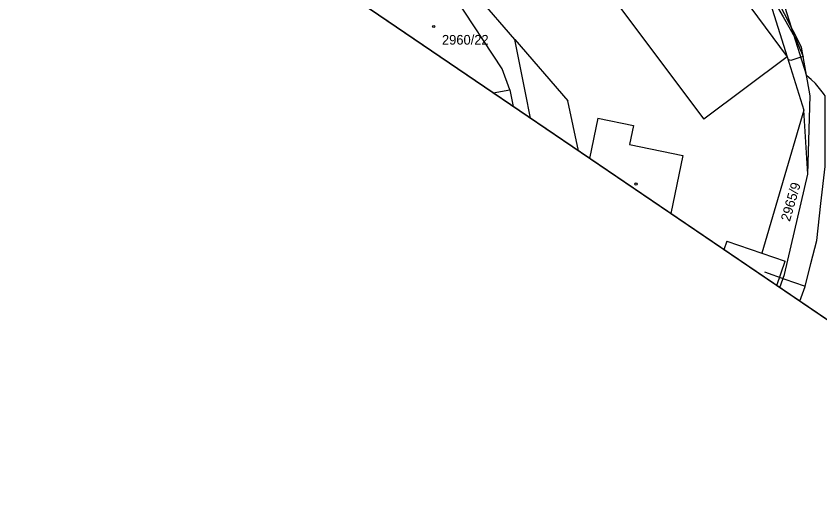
# Model space of a CAD drawing. Extents: x -620624 to -619936, y -1122925 to -1122325.
# Drawn here: x -620469.2 to -620344.4, y -1122791.5 to -1122714.1 of the extents above; entities that cross this region are included whole.
import ezdxf

# ---------------------------------------------------------------- set-up
doc = ezdxf.new("R2010")
doc.units = 0
for name, color, linetype in [('GasNet', 7, 'Continuous'), ('RÁMY', 7, 'Continuous'), ('VAS vodovod', 7, 'Continuous'), ('Vrstva 55', 7, 'Continuous'), ('Vrstva 57', 7, 'Continuous')]:
    doc.layers.add(name, color=color, linetype=linetype)

msp = doc.modelspace()

# ---------------------------------------------------------------- linework, layer by layer
at = {"layer": 'GasNet'}
msp.add_lwpolyline([(-620351, -1122709.02), (-620351.62, -1122709.36), (-620351.95, -1122709.89), (-620351.89, -1122710.61), (-620351.38, -1122712.06), (-620350.09, -1122714.22), (-620348.14, -1122717.64), (-620346.99, -1122720.36), (-620347.15, -1122720.39), (-620347.67, -1122720.57), (-620348.9, -1122720.99), (-620349.23, -1122720.89), (-620349.32, -1122720.93)], dxfattribs=at)
at = {"layer": 'RÁMY'}
for points in [[(-620540.39, -1122447.87), (-620019.21, -1122801.81), (-620102.64, -1122924.66), (-620623.82, -1122570.71)], [(-620366.66, -1122565.85), (-620019.21, -1122801.81), (-620102.64, -1122924.66), (-620450.09, -1122688.7)]]:
    msp.add_lwpolyline(points, close=True, dxfattribs=at)
at = {"layer": 'VAS vodovod'}
for points in [[(-620346.78, -1122722.2), (-620350.17, -1122711.62), (-620361.5, -1122697.5), (-620361.99, -1122696.76), (-620371.19, -1122688.51), (-620418.43, -1122648.88), (-620421.74, -1122646.95)], [(-620347.51, -1122758.36), (-620346.67, -1122756.05), (-620345.79, -1122752.48), (-620344.9, -1122748.91), (-620344.25, -1122743.18), (-620343.6, -1122737.45), (-620343.6, -1122731.96), (-620343.61, -1122726.46), (-620343.74, -1122726.27), (-620343.87, -1122726.08), (-620344.48, -1122725.31), (-620345.09, -1122724.54), (-620345.76, -1122723.95), (-620346.43, -1122723.35), (-620346.44, -1122723.33), (-620346.48, -1122723.26), (-620346.53, -1122723.17), (-620346.66, -1122722.69), (-620346.78, -1122722.2)], [(-620346.67, -1122756.05), (-620346.82, -1122756), (-620349.82, -1122754.95), (-620352.97, -1122753.85)]]:
    msp.add_lwpolyline(points, dxfattribs=at)
at = {"layer": 'Vrstva 55'}
for p, q in [((-620391.77, -1122717.74), (-620434.88, -1122667.63)), ((-620370.13, -1122692.59), (-620349.5, -1122720.4)), ((-620347.29, -1122718.92), (-620356.78, -1122700.2)), ((-620393.75, -1122722.26), (-620407.04, -1122702.06)), ((-620377.36, -1122710.19), (-620362.45, -1122730.09)), ((-620391.77, -1122717.74), (-620383.57, -1122727.26)), ((-620390.13, -1122725.98), (-620391.77, -1122717.74)), ((-620345.94, -1122726.44), (-620347.29, -1122718.92)), ((-620349.5, -1122720.4), (-620362.45, -1122730.09)), ((-620349.5, -1122720.4), (-620346.9, -1122728.66)), ((-620392.56, -1122725.51), (-620393.75, -1122722.26)), ((-620395.15, -1122726.01), (-620392.56, -1122725.51)), ((-620392.56, -1122725.51), (-620392.06, -1122728.11)), ((-620389.35, -1122729.95), (-620390.13, -1122725.98)), ((-620381.9, -1122735.01), (-620383.57, -1122727.26)), ((-620346.26, -1122738.61), (-620345.94, -1122726.44)), ((-620346.9, -1122728.66), (-620353.41, -1122750.9)), ((-620346.26, -1122738.61), (-620346.9, -1122728.66)), ((-620378.87, -1122729.94), (-620380.18, -1122736.18)), ((-620378.87, -1122729.94), (-620373.38, -1122731.07)), ((-620373.38, -1122731.07), (-620373.97, -1122734.01)), ((-620373.97, -1122734.01), (-620365.7, -1122735.74)), ((-620365.7, -1122735.74), (-620367.58, -1122744.74)), ((-620349.91, -1122754.18), (-620346.26, -1122738.61)), ((-620358.86, -1122749.03), (-620359.31, -1122750.35)), ((-620358.86, -1122749.03), (-620353.41, -1122750.9)), ((-620353.41, -1122750.9), (-620349.8, -1122752.13)), ((-620351.12, -1122755.91), (-620349.8, -1122752.13)), ((-620350.63, -1122756.24), (-620349.91, -1122754.18))]:
    msp.add_line(p, q, dxfattribs=at)
msp.add_lwpolyline([(-620422.85, -1122648.59), (-620419.73, -1122650.41), (-620372.55, -1122689.97), (-620363.06, -1122698.75), (-620352.08, -1122712.18), (-620349.5, -1122720.4)], dxfattribs=at)
at = {"layer": 'Vrstva 57'}
for centre in [(-620404.37, -1122715.7), (-620372.96, -1122740.15)]:
    msp.add_circle(centre, 0.175, dxfattribs=at)

# ---------------------------------------------------------------- texts
msp.add_text('2960/22', height=1.5, dxfattribs=at).set_placement((-620403.1, -1122718.51))
msp.add_text('2965/9', height=1.5, rotation=73.8221, dxfattribs=at).set_placement((-620349.08, -1122746.06))

doc.saveas('drawing.dxf')
